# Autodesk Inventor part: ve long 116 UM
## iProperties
Shininess: 41.0
Angle Display Precision: 2
Document Length Units: 11269
Document Angle Units: 11279
Document Time Units: 11290
Document Mass Units: 11283
Document Length Units Precision: 3
Document Angle Units Precision: 2
Part Number: ve long 116 UM
Material: Par défaut
Document SubType Name: Modeling
Density: 0.0
Volumn: 0.0
Area: 0.0
PropertySet Name: Model Information
Control State: 0
Master: False
Checked Out: False
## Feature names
1. Extrusion1
2. Perçage2 [Hole]
